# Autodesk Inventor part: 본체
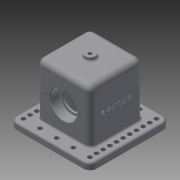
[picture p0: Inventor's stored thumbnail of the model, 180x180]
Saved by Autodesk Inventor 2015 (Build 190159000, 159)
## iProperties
Created: 2018-11
Part Number: 본체
Material: 일반
Document SubType Name: Modeling
Designer: now333
Density: 1 g/cm^3
Appearance: 기본값
Mass: 376.657 g
Surface Area: 777.001 cm^2
Volume: 376.657 cm^3
Author: now333
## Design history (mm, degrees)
sketch "스케치1"
  geometry: L1 (60, -60)-(-60, -60); L2 (-60, -60)-(-60, 60); L3 (-60, 60)-(60, 60); L4 (60, 60)-(60, -60); L5 (60, -60)-(-60, 60); L6 (-60, -60)-(60, 60); 1 further point
  constraints: 12 end point, 2 midpoint, 2 parallel, 1 horizontal, 1 perpendicular
  dimensions: "d0" = 120 distance of L1.start L1.end; "d1" = 120 distance of L3.end L1.start
extrude "돌출1" new body sketch "스케치1" distance "d2" = 10; taper "d3" = 0 deg
sketch "스케치2"
  geometry: L1 (40, -40)-(-40, -40); L2 (-40, -40)-(-40, 40); L3 (-40, 40)-(40, 40); L4 (40, 40)-(40, -40); L5 (40, -40)-(-40, 40); L6 (-40, -40)-(40, 40); 1 further point
  constraints: 12 end point, 2 midpoint, 2 parallel, 1 horizontal, 1 perpendicular
  dimensions: "d4" = 80 distance of L1.start L1.end; "d5" = 80 distance of L3.end L1.start
extrude "돌출2" join sketch "스케치2" distance "d6" = 80; taper "d7" = 0 deg
sketch "스케치4"
  geometry: L1 (30, 23)-(-30, 23); L2 (-30, 23)-(-30, -23); L3 (-30, -23)-(30, -23); L4 (30, -23)-(30, 23); L5 (30, 23)-(-30, -23); L6 (-30, 23)-(30, -23); 1 further point
  constraints: 12 end point, 2 midpoint, 2 parallel, 1 horizontal, 1 perpendicular
  dimensions: "d8" = 60 distance of L2.end L3.end; "d9" = 46 distance of L1.end L2.end
extrude "돌출3" cut sketch "스케치4" distance "d10" = 80; taper "d11" = 0 deg
sketch "스케치5"
  geometry: C1 r 7.5 at (0, 0); 1 further point
  constraints: 1 centre point, 1 coincident
  dimensions: "d12" = 15 diameter of C1
extrude "돌출4" join sketch "스케치5" distance "d13" = 5; taper "d14" = 0 deg
sketch "스케치6"
  geometry: C1 r 7.5 at (0, 0) reference
hole "구멍1" sketch "스케치6" at (0, 0) diameter "d15" = 4.917; stored, may be unused: countersink angle "d19" = 90 deg, drill point angle "d21" = 118 deg; dims "d16" = 20, "d17" = 4, "d18" = 2, "d20" = 17.1
sketch "스케치7"
  geometry: C1 r 20 at (40, 38); 1 further point
  constraints: 1 centre point, 1 vertical alignment
  dimensions: "d22" = 40 diameter of C1; "d23" = 48 distance of point (40, -10) C1.centre
extrude "돌출5" cut sketch "스케치7" distance "d24" = 14; taper "d25" = 0 deg
sketch "스케치8"
  geometry: L1 (60, -38)-(60, -48) reference; L2 (60, -48)-(-60, -48) reference; L3 (-60, -48)-(-60, -38) reference; L4 (-60, -38)-(-40, -38) reference; L5 (-40, -38)-(-40, 42) reference; L6 (-40, 42)-(40, 42) reference; L7 (40, 42)-(40, -38) reference; L8 (40, -38)-(60, -38) reference; C1 r 20 at (0, 0) reference; C2 r 16.5 at (0, 0); 1 further point
  constraints: 1 centre point, 1 coincident
  dimensions: "d26" = 33 diameter of C2
extrude "돌출6" cut sketch "스케치8" distance "d27" = 3; taper "d28" = 0 deg
sketch "스케치9"
  geometry: C1 r 20 at (40, 38) reference; 2 further points
  constraints: 1 vertical alignment
  dimensions: "d29" = 26 distance of C1.centre point (40, 64)
hole "구멍2" sketch "스케치9" at (40, 64) diameter "d30" = 3.242; stored, may be unused: countersink angle "d34" = 90 deg, drill point angle "d36" = 118 deg; dims "d31" = 8, "d32" = 4, "d33" = 2, "d35" = 10
fillet "모깎기1" dims "d41" = 10
sketch "스케치16"
  geometry: C1 r 3.3 at (-50, -50); A1 r 10 centre (-50, -50) between (-60, -50) and (-50, -60) reference; 1 further point
  constraints: 1 centre point, 1 coincident
  dimensions: "d64" = 6.6 diameter of C1
extrude "돌출8" cut sketch "스케치16" stored distance "d65" = 3; taper "d66" = 0 deg
sketch "스케치18"
  geometry: 2 further points
  constraints: 1 horizontal alignment, 1 other
  dimensions: "d73" = 48 distance of point (10, 40) point (-38, 40)
feature "엠보싱1" sketch "스케치18" dims "d0" = 120, "d1" = 120, "d8" = 60, "d9" = 46, "d74" = 0.5, "d75" = 0
fillet "모깎기2" dims "d76" = 8
fillet "모깎기3" dims "d77" = 3
fillet "모깎기4" dims "d78" = 3
fillet "모깎기5" dims "d79" = 3
chamfer "모따기1" distance "d80" = 1; stored, may be unused: second distance "d81" = 2, angle "d82" = 45 deg
fillet "모깎기6" dims "d83" = 0.6
node "솔리드1"
mirror "대칭1"
pattern_circular "원형 패턴1" dims angle "d38" = 360 deg
mirror "대칭2"
pattern_linear "직사각형 패턴2" dims "d69" = 25
pattern_linear "직사각형 패턴3" dims "d72" = 10
mirror "대칭4"
mirror "대칭5"
node "절단 모서리 투영1"
